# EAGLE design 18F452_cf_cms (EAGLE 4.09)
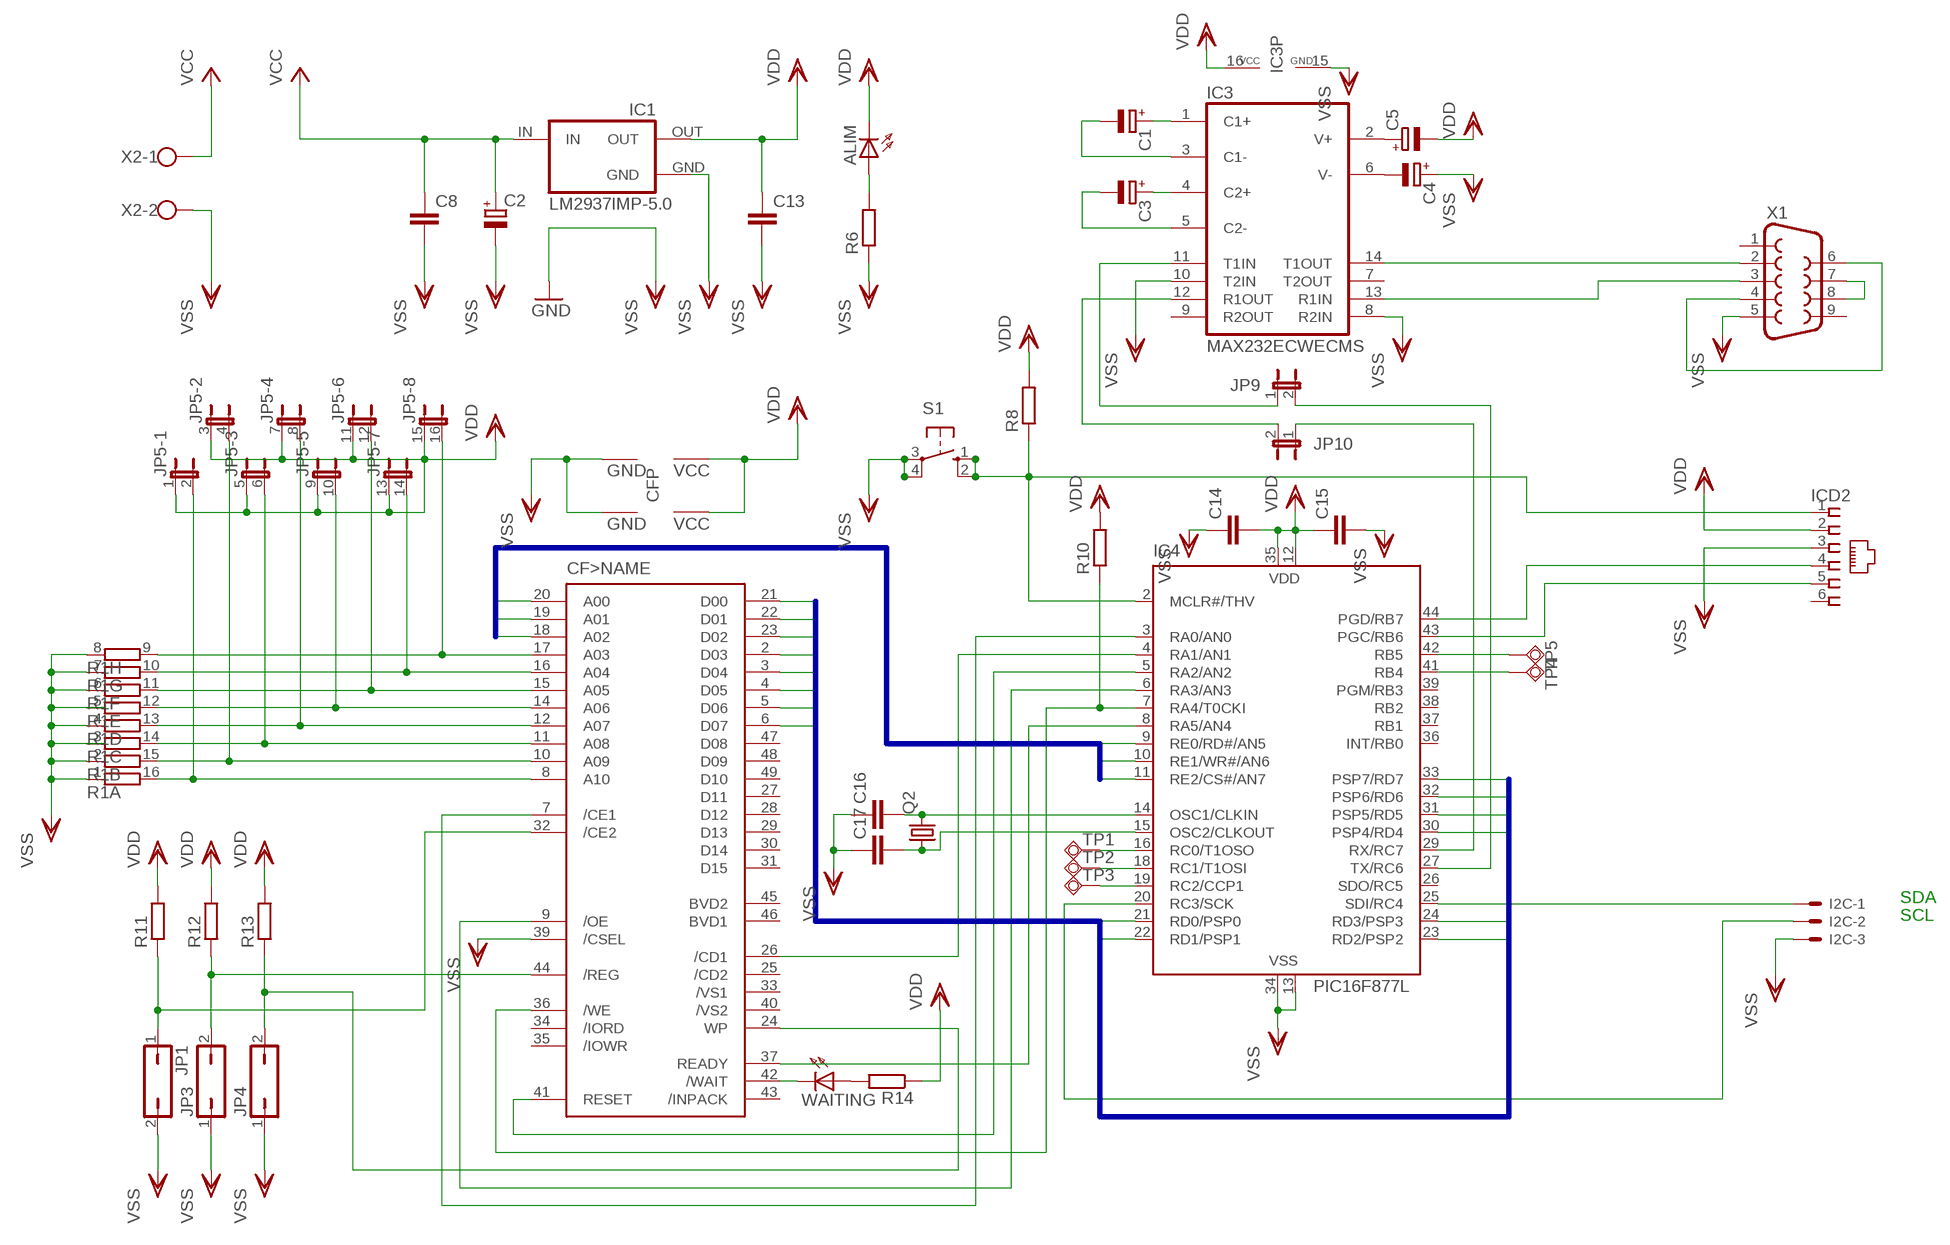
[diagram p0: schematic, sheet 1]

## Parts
ALIM  LEDSMT1206  [1206]
C1  CPOL-EUB  [PANASONIC_B]
C2  CPOL-EUB  [PANASONIC_B]
C3  CPOL-EUB  [PANASONIC_B]
C4  CPOL-EUB  [PANASONIC_B]
C5  CPOL-EUB  [PANASONIC_B]
C8  C-EUC0805  [C0805]
C13  C-EUC0805  [C0805]
C14  C-EUC0805  [C0805]
C15  C-EUC0805  [C0805]
C16  C-EUC0805  [C0805]
C17  C-EUC0805  [C0805]
CF  CF-CARD-MEMORY_MODE  [MI20-50PD-SF]
I2C  53047-03  [53047-03]
IC1  LM2937IMP-5.0  [SOT223]
IC3  MAX232ECWECMS  [SO16]
IC4  PIC16F877L  [PLCC-44]
ICD2  520250-3  [520250-3]
JP1  JP1Q  [JP1]
JP3  JP1Q  [JP1]
JP4  JP1Q  [JP1]
JP5  JP8QE  [JP8Q]
JP9  JP1E  [JP1]
JP10  JP1E  [JP1]
Q2  CRYTALSM49  [SM49]
R1  2NBS16-8E  [SO16]
R6  R-EU_R0805  [R0805]
R8  R-EU_R0805  [R0805]
R10  R-EU_R0805  [R0805]
R11  R-EU_R0805  [R0805]
R12  R-EU_R0805  [R0805]
R13  R-EU_R0805  [R0805]
R14  R-EU_R0805  [R0805]
S1  10-XX  [B3F-10XX]
TP1  B1,27  [B1,27]
TP2  B1,27  [B1,27]
TP3  B1,27  [B1,27]
TP4  B1,27  [B1,27]
TP5  B1,27  [B1,27]
WAITING  LEDSMT1206  [1206]
X1  F09H  [F09H]
X2  AK500/2  [AK500/2]

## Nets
N$1: C5.+ IC3.2(V+)
N$2: C4.- IC3.6(V-)
N$3: ALIM.A R6.2
N$7: I2C.1 IC4.25(SDI/RC4)
N$8: I2C.2 IC4.20(RC3/SCK)
N$9: CF.14(>NAME:A06) JP5.10 R1.12
N$12: R14.2 WAITING.A
N$15: IC4.16(RC0/T1OSO) TP1.PP
N$16: IC4.18(RC1/T1OSI) TP2.PP
N$17: IC4.19(RC2/CCP1) TP3.PP
N$18: IC4.41(RB4) TP4.PP
N$19: IC4.42(RB5) TP5.PP
N$23: IC4.2(MCLR#/THV) ICD2.1 R8.1 S1.1(S) S1.2(S1)
N$24: CF.24(>NAME:WP) JP4.2 R13.1
N$25: C1.+ IC3.1(C1+)
N$27: CF.32(>NAME:/CE2) JP1.1 R11.1
N$29: CF.17(>NAME:A03) JP5.16 R1.9
N$30: CF.16(>NAME:A04) JP5.14 R1.10
N$31: CF.44(>NAME:/REG) JP3.2 R12.1
N$32: CF.15(>NAME:A05) JP5.12 R1.11
N$33: X1.7 X1.8
N$35: CF.42(>NAME:/WAIT) WAITING.C
N$36: C1.- IC3.3(C1-)
N$37: C3.- IC3.5(C2-)
N$38: CF.12(>NAME:A07) JP5.8 R1.13
N$39: C3.+ IC3.4(C2+)
N$40: CF.11(>NAME:A08) JP5.6 R1.14
N$41: CF.10(>NAME:A09) JP5.4 R1.15
N$42: IC3.14(T1OUT) X1.2
N$44: IC3.13(R1IN) X1.3
N$45: X1.4 X1.6
N$51: IC3.12(R1OUT) JP10.2
N$52: IC3.11(T1IN) JP9.1
N$68: C16.2 IC4.14(OSC1/CLKIN) Q2.2
N$69: C17.2 IC4.15(OSC2/CLKOUT) Q2.1
N$A10: CF.8(>NAME:A10) JP5.2 R1.16
RA0: CF.7(>NAME:/CE1) IC4.3(RA0/AN0)
RA1: CF.26(>NAME:/CD1) IC4.4(RA1/AN1)
RA2: CF.41(>NAME:RESET) IC4.5(RA2/AN2)
RA3: CF.9(>NAME:/OE) IC4.6(RA3/AN3)
RA4: CF.36(>NAME:/WE) IC4.7(RA4/T0CKI) R10.1
RA5: CF.37(>NAME:READY) IC4.8(RA5/AN4)
RB6: IC4.43(PGC/RB6) ICD2.5
RB7: IC4.44(PGD/RB7) ICD2.4
RC6: IC4.27(TX/RC6) JP9.2
RC7: IC4.29(RX/RC7) JP10.1
RD0: CF.21(>NAME:D00) IC4.21(RD0/PSP0)
RD1: CF.22(>NAME:D01) IC4.22(RD1/PSP1)
RD2: CF.23(>NAME:D02) IC4.23(RD2/PSP2)
RD3: CF.2(>NAME:D03) IC4.24(RD3/PSP3)
RD4: CF.3(>NAME:D04) IC4.30(PSP4/RD4)
RD5: CF.4(>NAME:D05) IC4.31(PSP5/RD5)
RD6: CF.5(>NAME:D06) IC4.32(PSP6/RD6)
RD7: CF.6(>NAME:D07) IC4.33(PSP7/RD7)
RE0: CF.20(>NAME:A00) IC4.9(RE0/RD#/AN5)
RE1: CF.19(>NAME:A01) IC4.10(RE1/WR#/AN6)
RE2: CF.18(>NAME:A02) IC4.11(RE2/CS#/AN7)
VCC: C2.+ C8.1 IC1.IN X2.1
VDD: ALIM.C C5.- C13.1 C14.2 C15.1 CF.13(P:VCC1) CF.38(P:VCC2) IC1.OUT IC3.16(VCC) IC4.12(VDD) IC4.35(VDD) ICD2.2 JP5.1 JP5.3 JP5.5 JP5.7 JP5.9 JP5.11 JP5.13 JP5.15 R8.2 R10.2 R11.2 R12.2 R13.2 R14.1
VSS: C2.- C4.+ C8.2 C13.2 C14.1 C15.2 C16.1 C17.1 CF.1(P:GND1) CF.39(>NAME:/CSEL) CF.50(P:GND2) I2C.3 IC1.GND IC3.8(R2IN) IC3.10(T2IN) IC3.15(GND) IC4.13(VSS) IC4.34(VSS) ICD2.3 JP1.2 JP3.1 JP4.1 R1.1 R1.2 R1.4 R1.6 R1.7 R1.8 R6.1 S1.3(P) S1.4(P1) X1.5 X2.2 ; supply symbol labelled GND
Unconnected: CF.25(>NAME:/CD2) CF.27(>NAME:D11) CF.28(>NAME:D12) CF.29(>NAME:D13) CF.30(>NAME:D14) CF.31(>NAME:D15) CF.33(>NAME:/VS1) CF.34(>NAME:/IORD) CF.35(>NAME:/IOWR) CF.40(>NAME:/VS2) CF.43(>NAME:/INPACK) CF.45(>NAME:BVD2) CF.46(>NAME:BVD1) CF.47(>NAME:D08) CF.48(>NAME:D09) CF.49(>NAME:D10) IC3.7(T2OUT) IC3.9(R2OUT) IC4.26(SDO/RC5) IC4.36(INT/RB0) IC4.37(RB1) IC4.38(RB2) IC4.39(PGM/RB3) ICD2.6 R1.3 R1.5 X1.1 X1.9

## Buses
B$1
B$2

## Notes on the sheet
- SDA
- SCL

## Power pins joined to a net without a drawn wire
VSS: IC1.GND@(GND)

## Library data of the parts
ALIM WAITING = led:LED: LED
C1-C5 = rcl:CPOL-EU: POLARIZED CAPACITOR, European symbol
C8 C13-C17 = rcl:C-EU: CAPACITOR, European symbol
CF = hirose2:CF-CARD-MEMORY_MODE: Hirose Compact Flash Adapter Type I or II without Eject Button (Memory Mode)
I2C = con-molex:53?-03: CONNECTOR wire to board 1.25 mm (.049 inch) pitch header
IC1 = lm2937:LM2937IMP-*: 400 and 500 mA Low Dropout Voltage Regulator NATIONAL SEMICONDUCTOR created by Peter.Hofmann@ph-tronic.de 10-2004 Rev.0
IC3 = maxim:MAX232ECWE: RS232 TRANSEIVER
IC4 = microchip:PIC16F87*: MICROCONTROLLER
ICD2 = con-amp:520250-3: AMP connector
JP1 JP3 JP4 = jumper:JP1Q: JUMPER
JP5 = jumper:JP8QE: JUMPER
JP9 JP10 = jumper:JP1E: JUMPER
Q2 = crystal:CRYTAL: CRYSTAL
R1 = resistor-bourns:2NBS16-8E: BOURNS RESISTOR NETWORK
R6 R8 R10-R14 = rcl:R-EU_: RESISTOR, European symbol
S1 = switch-omron:10-XX: OMRON SWITCH
TP1-TP5 = testpad:B1,27: TEST PIN
X1 = con-subd:F09: SUB-D
X2 = con-ptr500:AK500/2: CONNECTOR

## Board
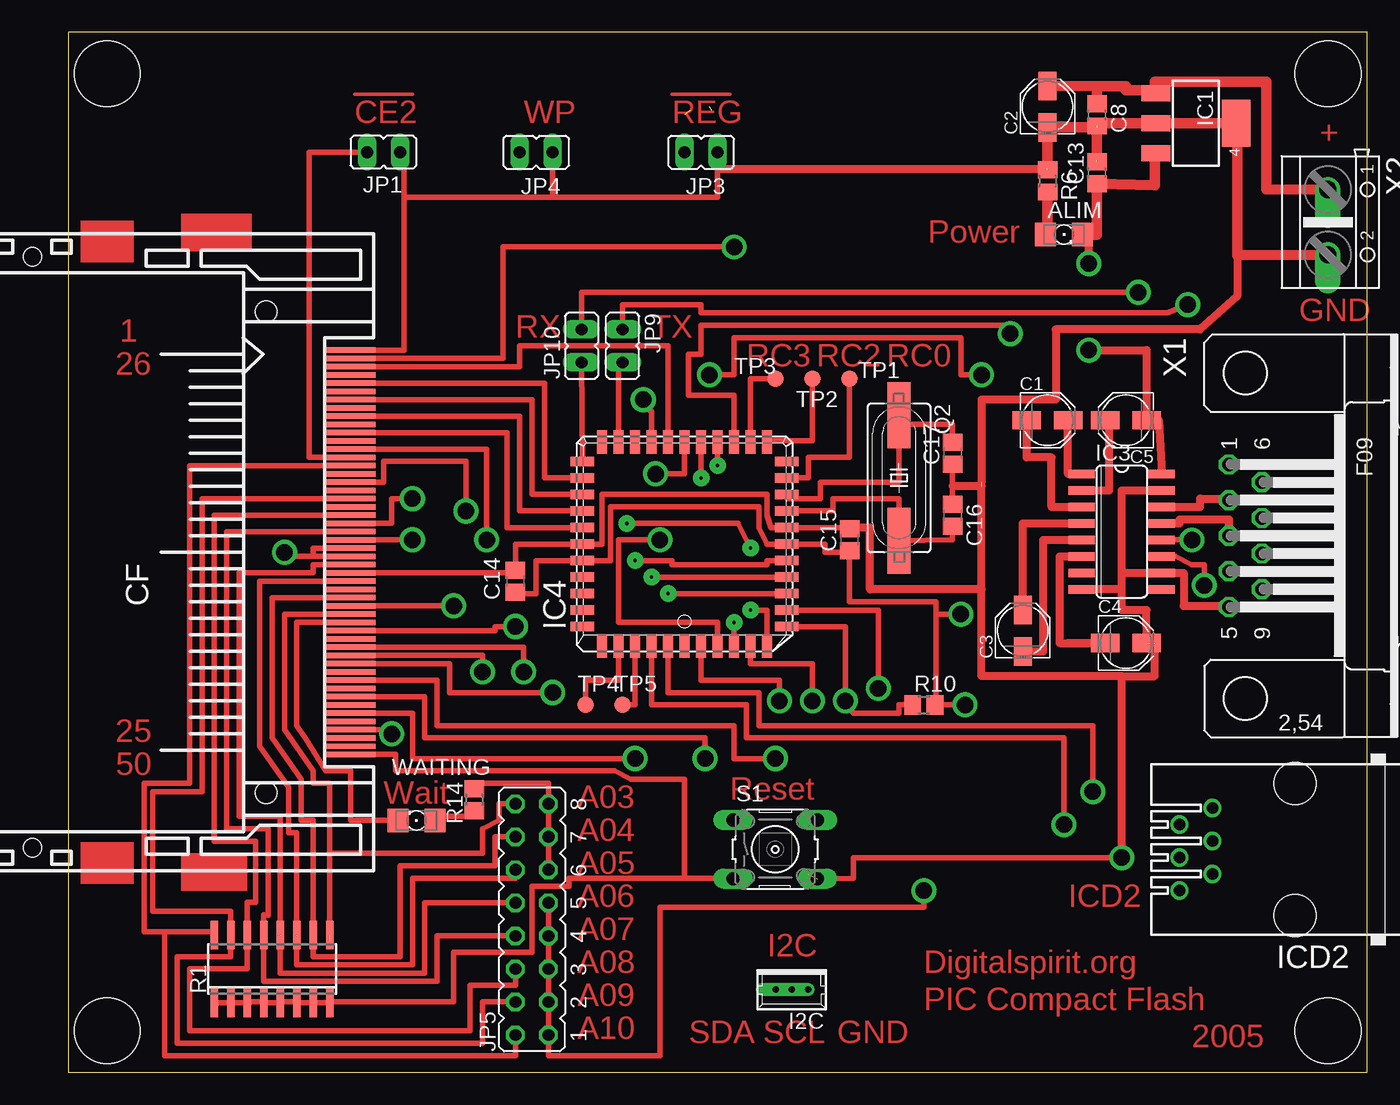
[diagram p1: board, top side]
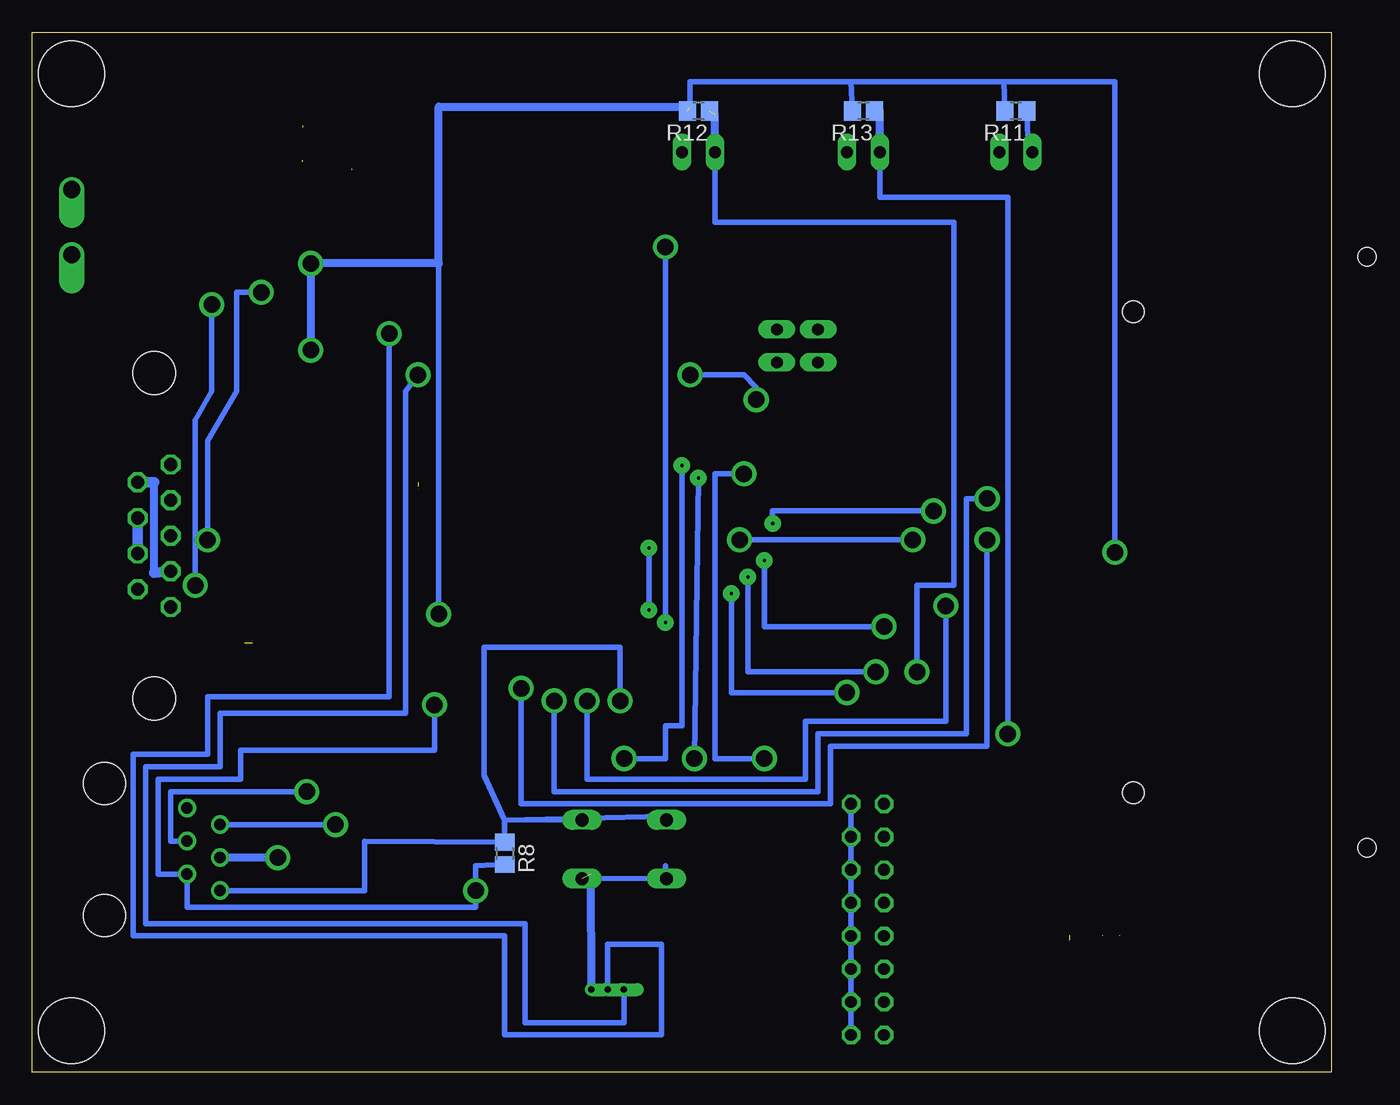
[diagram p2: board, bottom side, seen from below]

Size 100 x 80 mm. Coordinates in mm from the lower left corner, seen from the top.
Outline: 0,0 100,0 100,80 0,80 0,0
Copper layers used: Top, Bottom
Holes 5.08 mm at 3.01,76.83 3.01,3.17 96.99,3.17 96.99,76.83

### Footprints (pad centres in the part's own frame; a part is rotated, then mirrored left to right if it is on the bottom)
1206 = smd 1.6 x 1.803: A -1.422,0; C 1.422,0
PANASONIC_B = smd 2.2 x 1.4: + 1.6,0; - -1.6,0
C0805 = smd 1.3 x 1.5: 1 -0.85,0; 2 0.85,0
MI20-50PD-SF = smd 0.41 x 3.75: 1 15.557,-18.78; 2 14.287,-18.78; 3 13.018,-18.78; 4 11.748,-18.78; 5 10.477,-18.78; 6 9.207,-18.78; 7 7.938,-18.78; 8 6.668,-18.78; 9 5.397,-18.78; 10 4.128,-18.78; 11 2.857,-18.78; 12 1.587,-18.78; 13 0.318,-18.78; 14 -0.953,-18.78; 15 -2.223,-18.78; 16 -3.493,-18.78; 17 -4.763,-18.78; 18 -6.032,-18.78; 19 -7.303,-18.78; 20 -8.572,-18.78; 21 -9.842,-18.78; 22 -11.113,-18.78; 23 -12.383,-18.78; 24 -13.652,-18.78; 25 -14.922,-18.78; 26 14.922,-18.78; 27 13.652,-18.78; 28 12.383,-18.78; 29 11.113,-18.78; 30 9.842,-18.78; 31 8.572,-18.78; 32 7.303,-18.78; 33 6.032,-18.78; 34 4.763,-18.78; 35 3.493,-18.78; 36 2.223,-18.78; 37 0.953,-18.78; 38 -0.318,-18.78; 39 -1.587,-18.78; 40 -2.857,-18.78; 41 -4.128,-18.78; 42 -5.397,-18.78; 43 -6.668,-18.78; 44 -7.938,-18.78; 45 -9.207,-18.78; 46 -10.477,-18.78; 47 -11.748,-18.78; 48 -13.018,-18.78; 49 -14.287,-18.78; 50 -15.557,-18.78 | hole 1.676: 18.5,-12.25; -18.5,-12.25 | hole 1.422: -22.75,5.75; 22.75,5.75
53047-03 = drill 0.5 pad 0.698 offset: 1 1.25,0; 2 0,0; 3 -1.25,0
SOT223 = smd 1.219 x 2.235: GND 0,-3.099; IN -2.311,-3.099; OUT 2.311,-3.099 | smd 3.6 x 2.2: GND@ 0,3.099
SO16 = smd 0.66 x 2.032: 1 -4.445,-3.073; 2 -3.175,-3.073; 3 -1.905,-3.073; 4 -0.635,-3.073; 5 0.635,-3.073; 6 1.905,-3.073; 7 3.175,-3.073; 8 4.445,-3.073; 9 4.445,3.073; 10 3.175,3.073; 11 1.905,3.073; 12 0.635,3.073; 13 -0.635,3.073; 14 -1.905,3.073; 15 -3.175,3.073; 16 -4.445,3.073
PLCC-44 = smd 1.8 x 0.76: 1 -7.86,0; 2 -7.86,-1.27; 3 -7.86,-2.54; 4 -7.86,-3.81; 5 -7.86,-5.08; 6 -7.86,-6.35; 18 7.86,-6.35; 19 7.86,-5.08; 20 7.86,-3.81; 21 7.86,-2.54; 22 7.86,-1.27; 23 7.86,0; 24 7.86,1.27; 25 7.86,2.54; 26 7.86,3.81; 27 7.86,5.08; 28 7.86,6.35; 40 -7.86,6.35; 41 -7.86,5.08; 42 -7.86,3.81; 43 -7.86,2.54; 44 -7.86,1.27 | smd 0.76 x 1.8: 7 -6.35,-7.86; 8 -5.08,-7.86; 9 -3.81,-7.86; 10 -2.54,-7.86; 11 -1.27,-7.86; 12 0,-7.86; 13 1.27,-7.86; 14 2.54,-7.86; 15 3.81,-7.86; 16 5.08,-7.86; 17 6.35,-7.86; 29 6.35,7.86; 30 5.08,7.86; 31 3.81,7.86; 32 2.54,7.86; 33 1.27,7.86; 34 0,7.86; 35 -1.27,7.86; 36 -2.54,7.86; 37 -3.81,7.86; 38 -5.08,7.86; 39 -6.35,7.86
520250-3 = drill 0.889 round: 1 -3.175,8.89; 2 -1.905,6.35; 3 -0.635,8.89; 4 0.635,6.35; 5 1.905,8.89; 6 3.175,6.35 | hole 3.251: -5.08,0; 5.08,0
JP1 = drill 0.914 long: 1 0,-1.27; 2 0,1.27
JP8Q = drill 0.914 octagon: 1 -8.89,-1.27; 2 -8.89,1.27; 3 -6.35,-1.27; 4 -6.35,1.27; 5 -3.81,-1.27; 6 -3.81,1.27; 7 -1.27,-1.27; 8 -1.27,1.27; 9 1.27,-1.27; 10 1.27,1.27; 11 3.81,-1.27; 12 3.81,1.27; 13 6.35,-1.27; 14 6.35,1.27; 15 8.89,-1.27; 16 8.89,1.27
SM49 = smd 5.08 x 1.778: 1 -4.826,0; 2 4.826,0
SO16' = smd 0.6 x 2.2: 1 -4.445,-2.6; 2 -3.175,-2.6; 3 -1.905,-2.6; 4 -0.635,-2.6; 5 0.635,-2.6; 6 1.905,-2.6; 7 3.175,-2.6; 8 4.445,-2.6; 9 4.445,2.6; 10 3.175,2.6; 11 1.905,2.6; 12 0.635,2.6; 13 -0.635,2.6; 14 -1.905,2.6; 15 -3.175,2.6; 16 -4.445,2.6
R0805 = smd 1.3 x 1.5: 1 -0.85,0; 2 0.85,0
B3F-10XX = drill 1.016 long: 1 -3.251,2.261; 2 3.251,2.261; 3 -3.251,-2.261; 4 3.251,-2.261
B1,27 = smd 1.27 x 1.27: PP 0,0
F09H = drill 1.016 octagon: 1 -5.486,-1.27; 2 -2.743,-1.27; 3 0,-1.27; 4 2.743,-1.27; 5 5.486,-1.27; 6 -4.115,1.27; 7 -1.372,1.27; 8 1.372,1.27; 9 4.115,1.27 | hole 3.302: -12.522,0; 12.522,0
AK500/2 = drill 1.321 offset: 1 -2.515,0; 2 2.515,0

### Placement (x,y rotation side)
ALIM  76.67,64.45 0 top
C1  75.4,50.16 0 top
C2  75.4,74.29 90 top
C3  73.5,33.97 90 top
C4  81.43,33.02 0 top
C5  81.43,50.16 180 top
C8  79.21,73.66 270 top
C13  79.21,69.21 90 top
C14  34.44,37.78 270 top
C15  60.16,40.95 90 top
C16  68.1,42.86 270 top
C17  68.1,47.62 90 top
CF  3.01,40 90 top
I2C  55.71,6.34 180 top
IC1  86.83,73.02 270 top
IC3  81.11,41.59 270 top
IC4  47.46,40.64 90 top
ICD2  94.45,17.14 90 top
JP1  24.28,70.8 270 top
JP3  48.73,70.8 90 top
JP4  36.03,70.8 90 top
JP5  35.71,11.74 90 top
JP9  42.7,55.88 180 top
JP10  39.52,55.88 0 top
Q2  63.97,45.72 270 top
R1  [SO16']  15.71,7.93 0 top
R6  75.4,68.57 270 top
R8  63.65,16.82 270 bottom
R10  65.88,28.25 0 top
R11  24.28,73.97 180 bottom
R12  48.73,73.97 180 bottom
R13  36.03,73.97 180 bottom
R14  31.27,20.95 270 top
S1  54.45,17.14 0 top
TP1  60.16,53.34 0 top
TP2  57.3,53.34 0 top
TP3  54.45,53.34 0 top
TP4  39.84,28.25 0 top
TP5  42.7,28.25 0 top
WAITING  26.82,19.36 180 top
X1  90.64,41.27 270 top
X2  96.99,65.4 270 top

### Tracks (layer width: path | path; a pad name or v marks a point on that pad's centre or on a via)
N$1
  Top 0.61: IC3.2 80.16,44.76 80.16,50.16 C5.+
N$2
  Top 0.61: IC3.6 76.35,39.68 76.35,33.02 C4.- 76.99,33.02
N$3
  Top 0.813: ALIM.A 75.4,64.45 R6.2
N$7  (via drill 1.27 pad 1.93)
  Top 0.406: v44.28,51.75 44.28,51.43 44.92,50.8 IC4.25 | v70.32,53.65 68.73,53.65 68.73,56.51 51.27,56.51 51.27,53.65 v49.37,53.65
  Bottom 0.406: v70.32,53.65 71.27,52.38 71.27,27.62 85.56,27.62 85.56,23.49 91.28,23.49 91.28,11.43 62.06,11.43 62.06,3.8 54.45,3.8 54.45,6.34 I2C.1 | v49.37,53.65 45.24,53.65 44.28,52.7 v44.28,51.75
N$8  (via drill 1.27 pad 1.93)
  Top 0.406: IC4.20 51.27,52.07 47.78,52.07 47.78,55.24 48.73,55.24 48.73,57.46 72.54,57.46 v72.54,56.83
  Bottom 0.406: v72.54,56.83 72.54,28.89 86.51,28.89 86.51,24.44 92.23,24.44 92.23,10.47 63.65,10.47 63.65,2.85 51.59,2.85 51.59,9.84 55.71,9.84 I2C.2 55.71,6.03
N$9  (1 unrouted)
  Top 0.406: CF.14 18.88,39.05 18.88,38.41 13.17,38.41 13.17,19.68 16.34,19.68 R1.12 | JP5.10 27.46,13.01 27.46,7.62 16.34,7.62 16.34,10.47
N$12
  Top 0.406: R14.2 31.27,19.68 28.41,19.68 WAITING.A
N$15
  Top 0.406: IC4.16 56.98,45.72 56.98,47.3 60.16,47.3 TP1.PP
N$16
  Top 0.406: TP2.PP 57.3,48.57 53.81,48.57 IC4.18
N$17
  Top 0.406: TP3.PP 52.54,53.34 IC4.19
N$18
  Top 0.406: IC4.41 42.38,30.16 39.84,30.16 TP4.PP
N$19
  Top 0.406: IC4.42 43.65,28.25 TP5.PP
N$20
  Top 0.254: 22.06,75.24 26.5,75.24
N$21
  Top 0.254: 46.51,75.24 50.95,75.24
N$23  (via drill 1.27 pad 1.93)
  Top 0.406: IC4.2 48.73,30.16 54.76,30.16 v54.76,28.57
  Bottom 0.406: v54.76,28.57 54.76,32.7 65.24,32.7 65.24,22.86 63.65,19.36 | S1.1 51.27,19.68 63.65,19.36 | 63.65,19.36 S1.2 | R8.1 63.65,17.46 | 63.65,19.36 R8.1 | R8.1 74.45,17.77 74.45,13.97 ICD2.1
N$24  (via drill 1.27 pad 1.93)
  Top 0.406: CF.24 23.96,26.35 v24.92,26.03
  Bottom 0.406: v24.92,26.03 24.92,67.3 34.76,67.3 JP4.2
  Bottom 0.61: R13.1 34.76,73.97 JP4.2
N$25
  Top 0.61: IC3.1 76.99,46.03 76.99,50.16 C1.+
N$27
  Top 0.406: CF.32 18.57,47.3 18.57,70.8 JP1.1
  Top 0.61: JP1.1 23.01,70.48
  Bottom 0.406: JP1.1 23.33,70.8 R11.1
N$29  (1 unrouted)
  Top 0.406: CF.17 16.66,35.24 16.66,26.35 18.88,23.17 18.88,22.22 20.15,22.22 20.15,16.82 | 20.15,10.16 20.15,16.82 | JP5.16 33.17,20.63 33.17,19.36 31.9,18.73 31.9,16.82 20.15,16.82
N$30
  Top 0.406: CF.16 15.71,36.51 15.71,25.71 17.93,22.54 17.93,19.36 18.88,19.36 18.88,10.79 | R1.10 18.88,10.79 | JP5.14 32.85,18.09 32.85,15.87 25.55,15.87 25.55,8.89 18.88,8.89 18.88,10.79
N$31  (via drill 1.27 pad 1.93)  (1 unrouted)
  Top 0.406: CF.44 31.9,32.06 v31.9,30.79
  Bottom 0.406: v31.9,30.79 31.9,37.46 29.04,37.46 29.04,65.4 47.46,65.4 JP3.2
  Bottom 0.61: JP3.2 47.46,73.66
N$32  (1 unrouted)
  Top 0.406: CF.15 14.76,37.78 14.76,25.08 16.98,21.9 16.98,18.41 17.61,18.41 R1.11 | JP5.12 34.44,14.92 26.5,14.92 26.5,8.25 17.61,8.25 17.61,10.47
N$33
  Bottom 0.813: 91.91,39.68 X1.8 X1.7
N$35
  Top 0.406: WAITING.C 21.74,19.36 21.74,23.17 19.84,23.17 18.25,25.71 17.61,26.66 17.61,34.6 CF.42
N$36
  Top 0.61: C1.- 73.81,47.3 75.72,47.3 75.72,43.49 IC3.3
N$37
  Top 0.61: IC3.5 75.08,40.95 75.08,32.38 73.18,32.38 C3.-
N$38
  Top 0.406: CF.12 12.22,41.59 12.22,18.73 15.39,18.73 15.39,12.06 15.08,12.12 R1.13 15.08,6.98 28.41,6.98 28.41,10.47 JP5.8
N$39
  Top 0.61: C3.+ 73.5,42.22 IC3.4
N$40
  Top 0.406: CF.11 11.27,42.86 11.27,17.77 14.44,17.77 14.44,13.07 13.81,13.07 R1.14 13.81,7.93 9.36,7.93 9.36,3.17 30.95,3.17 30.95,6.66 34.44,6.66 JP5.6
N$41
  Top 0.406: CF.10 10.31,44.13 10.31,21.58 6.5,21.58 6.5,12.38 12.54,12.38 R1.15 12.54,8.89 8.41,8.89 8.41,2.22 31.9,2.22 31.9,5.39 JP5.4
N$42
  Top 0.61: IC3.14 87.15,43.49 87.15,44.13 89.37,44.13 X1.2
N$44
  Top 0.61: IC3.13 85.56,42.22 85.56,42.54 89.37,42.54 X1.3
N$45
  Bottom 0.61: 90.64,38.41 90.64,45.4
  Bottom 0.813: 90.64,45.4 X1.6 | X1.4 90.64,38.41
N$51  (via drill 1.27 pad 1.68, 1.27 pad 1.93)
  Top 0.406: JP10.2 39.52,60 v82.39,60 | v86.51,40.95 IC3.12
  Bottom 0.406: v82.39,60 84.29,60 84.29,52.38 86.51,48.57 v86.51,40.95
N$52  (via drill 1.27 pad 1.68, 1.27 pad 1.93)
  Top 0.406: JP9.1 42.7,59.05 48.73,59.05 48.73,58.41 84.61,58.41 v86.19,59.05 | v87.47,37.46 87.47,39.05 86.51,39.05 85.24,39.68 IC3.11
  Bottom 0.406: v86.19,59.05 86.19,52.38 87.47,50.16 v87.47,37.46
N$68
  Top 0.406: IC4.14 58.89,43.18 58.89,44.13 63.97,44.13 Q2.2 68.1,40.95 C16.2 68.1,42.22
N$69
  Top 0.406: C17.2 68.1,49.84 63.97,49.84 Q2.1 63.97,45.4 57.94,45.4 57.94,44.13 55.4,44.13 IC4.15
N$A10
  Top 0.406: CF.8 9.36,46.67 9.36,22.22 | 5.87,10.79 5.87,22.22 9.36,22.22 | 9.36,22.22 9.36,22.54 | R1.16 11.27,10.79 5.87,10.79 | 5.87,10.79 7.46,10.79 7.46,1.27 34.44,1.27 JP5.2
RA0  (via drill 1.27 pad 1.93)
  Top 0.406: CF.7 32.22,47.94 v32.22,40.95 | IC4.3 50,34.6 42.38,34.6 42.38,40.95 v45.55,40.95
  Bottom 0.406: v32.22,40.95 v45.55,40.95
RA1  (via drill 0.25 pad 1.27, 1.27 pad 1.42)
  Top 0.406: CF.26 33.49,54.92 33.49,63.5 v51.27,63.5 | 51.27,32.7 IC4.4 v51.27,34.6
  Bottom 0.406: v51.27,63.5 v51.27,34.6
RA2  (via drill 1.27 pad 1.93)
  Top 0.406: IC4.5 52.54,31.43 57.3,31.43 v57.3,28.57 | CF.41 v29.68,35.87
  Bottom 0.406: v29.68,35.87 29.68,26.98 40.48,26.98 40.48,22.54 57.3,22.54 v57.3,28.57
RA3  (via drill 0.25 pad 1.27, 1.27 pad 1.93)
  Top 0.406: CF.9 24.28,45.4 24.28,46.98 30.63,46.98 v30.63,43.18 | v43.02,42.22 51.59,42.22 v52.54,40.32 | v52.54,35.55 53.81,35.55 IC4.6 53.81,32.7
  Bottom 0.406: v30.63,43.18 43.02,43.18 v43.02,42.22 | v52.54,40.32 v52.54,35.55
RA4  (via drill 1.27 pad 1.93)
  Top 0.406: CF.36 24.92,42.22 24.92,44.13 v26.5,44.13 | 55.08,34.29 IC4.7 59.84,34.29 v59.84,28.57 60.48,27.62 63.97,27.62 63.97,28.25 R10.1
  Bottom 0.406: v26.5,44.13 28.09,44.13 28.09,26.03 39.52,26.03 39.52,21.58 59.84,21.58 v59.84,28.57
RA5  (via drill 1.27 pad 1.93)
  Top 0.406: v26.5,40.95 CF.37 | 55.08,35.55 IC4.8 62.38,35.55 v62.38,29.52
  Bottom 0.406: v26.5,40.95 26.5,25.08 38.57,25.08 38.57,20.63 62.38,20.63 v62.38,29.52
RB6  (via drill 1.27 pad 1.93)
  Top 0.406: IC4.43 44.92,28.25 52.22,28.25 52.22,25.71 76.67,25.71 v76.67,19.04
  Bottom 0.406: v76.67,19.04 ICD2.5
RB7  (via drill 1.27 pad 1.93)
  Top 0.406: IC4.44 46.19,29.2 53.17,29.2 53.17,26.66 78.89,26.66 v78.89,21.58
  Bottom 0.406: ICD2.4 89.37,17.77 89.37,21.58 v78.89,21.58
RC6
  Top 0.406: IC4.27 42.38,54.61 JP9.2
RC7
  Top 0.406: IC4.29 JP10.1
RD0  (via drill 0.25 pad 1.27, 1.27 pad 1.93)
  Top 0.406: v50,46.67 IC4.21 | 21.74,30.16 CF.21 28.41,30.16 28.41,26.66 51.27,26.66 51.27,24.12 v54.45,24.12
  Bottom 0.406: v54.45,24.12 51.27,24.12 51.27,26.66 50,26.66 v50,46.67
RD1  (via drill 0.25 pad 1.27, 1.27 pad 1.93)
  Top 0.406: CF.22 27.46,28.89 27.46,25.71 49.05,25.71 v49.05,24.12 | v48.73,45.72 IC4.22
  Bottom 0.406: v49.05,24.12 v48.73,45.72
RD2  (via drill 1.27 pad 1.93)
  Top 0.406: CF.23 26.5,27.62 26.5,24.12 v43.65,24.12 | 47.46,48.57 IC4.23 47.46,46.03 v45.24,46.03
  Bottom 0.406: v43.65,24.12 47.46,24.12 47.46,46.03 v45.24,46.03
RD3
  Top 0.406: CF.2 34.76,54.29 34.76,55.88 46.19,55.88 IC4.24
RD4
  Top 0.406: CF.3 36.66,53.02 36.66,45.72 IC4.30 39.84,45.72
RD5
  Top 0.406: IC4.31 35.71,44.45 35.71,51.75 CF.4 21.74,51.75
RD6
  Top 0.406: IC4.32 34.76,43.18 34.76,50.48 CF.5
RD7
  Top 0.406: IC4.33 33.81,41.91 33.81,49.21 CF.6 21.74,49.21
RE0  (via drill 0.25 pad 1.27, 1.27 pad 1.93)
  Top 0.406: CF.20 29.36,31.43 29.36,29.2 v37.3,29.2 | v46.19,36.83 IC4.9
  Bottom 0.406: v37.3,29.2 46.19,29.2 v46.19,36.83
RE1  (via drill 0.25 pad 1.27, 1.27 pad 1.93)
  Top 0.406: v44.92,38.1 IC4.10 | CF.19 35.08,32.7 v35.08,30.79
  Bottom 0.406: v35.08,30.79 44.92,30.79 v44.92,38.1
RE2  (via drill 0.25 pad 1.27, 1.27 pad 1.93)
  Top 0.406: v43.65,39.37 46.51,39.37 46.51,39.05 53.81,39.05 53.81,39.37 IC4.11 | CF.18 32.85,33.97 32.85,34.29 v34.44,34.29
  Bottom 0.406: v34.44,34.29 43.65,34.29 v43.65,39.37
VCC
  Top 0.813: C2.+ 79.21,75.88 | 79.21,75.88 C8.1 | 79.21,75.88 81.43,75.88 81.43,75.56 83.66,75.56 IC1.IN 83.66,75.24 83.66,76.19 92.23,76.19 92.23,67.94 X2.1
VDD  (via drill 1.27 pad 1.93)  (1 unrouted)
  Top 0.406: CF.13 18.88,40.32 18.88,39.68 | 21.74,39.68 CF.38 18.88,39.68 | 60.16,40 C15.1 | 60.16,40 58.25,40 58.25,40.64 IC4.12 53.81,40.64 53.17,41.91 53.17,43.49 41.74,43.49 41.74,39.37 IC4.35 36.03,39.37 36.03,36.83 34.44,36.83 C14.2 | 60.16,40 60.16,36.19 66.83,36.19 66.83,35.24 | 66.83,28.25 66.83,35.24 | 18.88,39.68 17.61,39.68 v16.66,40 | v69.05,28.25 66.83,28.25 | 66.83,28.25 R10.2 | v65.88,13.97 65.88,12.7 45.55,12.7 45.55,1.27 36.98,1.27 JP5.1 36.98,5.08 | R14.1 31.27,22.22 36.98,22.22 JP5.15 JP5.13 JP5.11 | 66.83,35.24 v68.73,35.24 | JP5.5 36.98,8.25 | JP5.3 JP5.5 | JP5.5 JP5.7 JP5.9
  Top 0.61: IC3.16 83.97,50.16 C5.- | C5.- | v78.58,62.23 78.58,64.45 | v78.58,55.56 83.02,55.56 83.02,49.84 C5.-
  Top 0.813: ALIM.C 78.58,64.45 79.21,64.45 C13.1 83.66,68.26 83.66,70.48 IC1.OUT
  Bottom 0.406: 36.98,76.19 25.23,76.19 | 36.98,76.19 49.37,76.19 49.37,74.29 | 25.23,76.19 R11.2 | 36.98,76.19 R13.2 | R8.2 65.88,15.87 v65.88,13.97 65.88,12.7 88.1,12.7 ICD2.2 90.32,15.24 90.32,22.54 83.97,22.54 83.97,24.76 69.05,24.76 v69.05,28.25 | v16.66,40 16.66,76.19 25.23,76.19 | v68.73,35.24 68.73,62.23 | JP5.3 JP5.1 JP5.5 JP5.9 36.98,15.87 | 36.98,15.87 JP5.13 JP5.15 | 36.98,15.87 JP5.11
  Bottom 0.61: 49.37,74.29 68.73,74.29 68.73,62.23 v78.58,62.23 v78.58,55.56
VSS  (via drill 1.27 pad 1.93)  (6 unrouted)
  Top 0.406: 21.74,24.44 CF.50 25.23,24.44 25.23,23.17 42.06,23.17 43.33,22.54 47.46,22.54 47.46,14.92 | CF.1 25.87,55.56 25.87,67.3 | C15.2 60.16,41.91 IC4.13 54.13,41.91 53.81,42.86 53.81,44.45 41.11,44.45 41.11,40.64 39.84,40.64 | C17.1 68.1,45.08 C16.1 | JP1.2 25.87,70.8 25.87,67.3 | 25.87,67.3 37.3,67.3 | 37.3,67.3 JP4.1 | 37.3,67.3 50,67.3 50,69.53 | CF.39 34.44,38.41 C14.1 34.44,40.64 39.84,40.64 | 39.84,40.64 IC4.34 | S1.4 60.48,14.92 60.48,16.5 v81.11,16.5 | S1.3 51.59,14.92 47.46,14.92 | 47.46,14.92 38.57,14.92 38.57,14.28 35.71,14.28 35.71,9.2 29.68,9.2 29.68,5.39 20.15,5.39 R1.8 R1.7 | R1.2 R1.1 | R1.2 12.54,5.39 | R1.2 13.81,5.33 13.81,5.39 15.08,5.39 R1.4 16.34,5.33 16.34,5.39 17.61,5.39 R1.6 R1.7 | R1.7 18.88,5.39
  Top 0.61: X1.5 89.37,35.87 85.88,35.87 85.88,38.41 IC3.10 81.11,38.41 | 81.11,38.41 81.11,44.76 IC3.15 84.61,44.76 | 81.11,37.14 81.11,38.41 | 81.11,37.14 IC3.8 | C4.+ 83.02,35.55 81.11,35.55 81.11,37.14 | 60.16,41.91 61.75,41.91 61.75,37.14 70.32,37.14 | 70.32,37.14 70.32,45.08 68.1,45.08 | 70.32,37.14 70.32,30.47 81.11,30.47 | 83.66,33.02 83.66,30.47 81.11,30.47 | 75.4,69.53 50,69.53 JP3.1 | v81.11,16.5 81.11,30.47 | 70.32,45.4 70.32,51.75 76.03,51.75 76.03,57.15 87.15,57.15 90,59.69 90,62.86
  Top 0.813: 79.21,72.7 79.21,70.16 | 79.21,72.7 79.21,73.02 IC1.GND IC1.GND@ 90,72.7 90,62.86 X2.2 | 75.4,69.53 C2.- 79.21,72.7
  Bottom 0.406: 51.27,14.92 S1.4 | S1.3 51.27,14.92 | 51.27,14.92 51.27,15.87
  Bottom 0.61: I2C.3 56.98,15.24 | v81.11,16.5 ICD2.3
(copper drawn outside any net)
  shapes: Top area x2

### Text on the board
Top: CE2 | WP | REG | + | Power | GND | 1 | RX | TX | RC3 | RC2 | RC0 | 26 | 25 | 50 | Wait | A03 | Reset | A04 | A05 | A06 | ICD2 | A07 | I2C | A08 | Digitalspirit.org | A09 | PIC Compact Flash | A10 | SDA | SCL | GND | 2005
